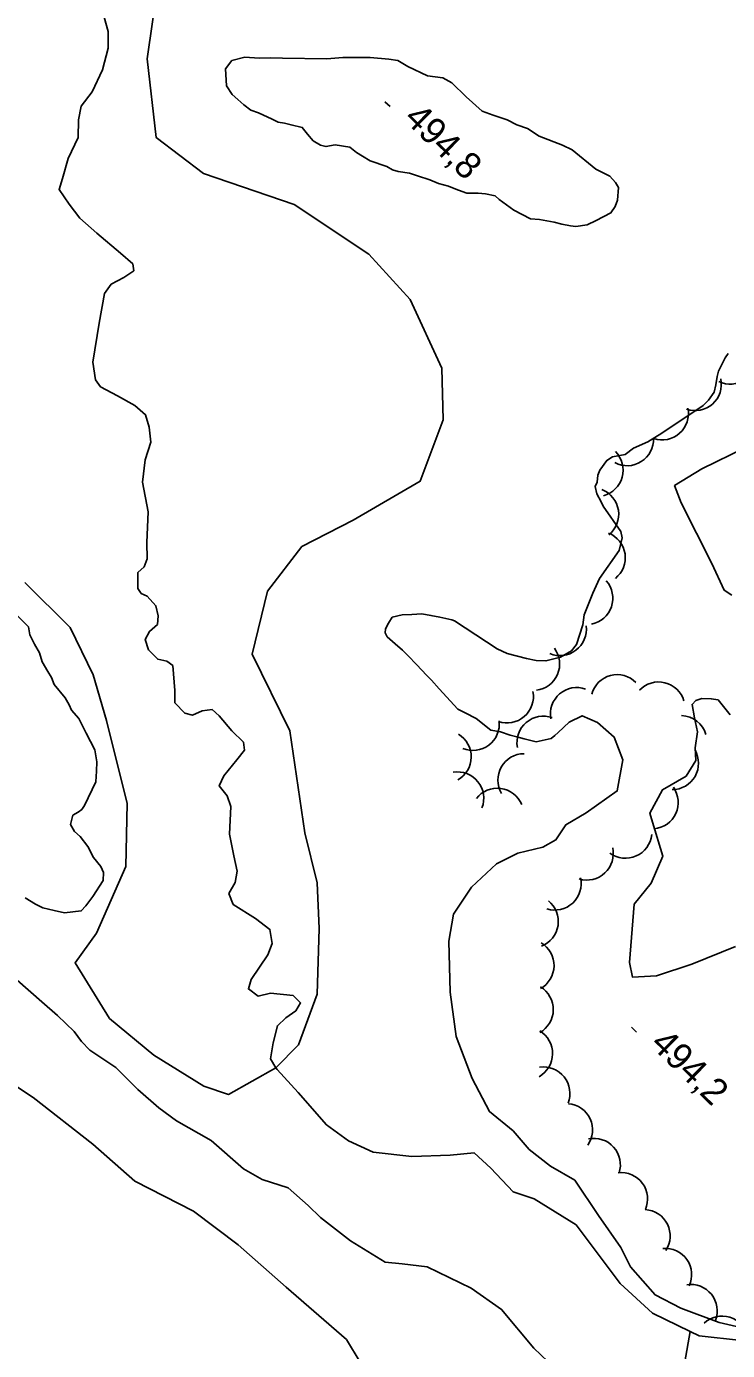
# Model space of a CAD drawing. Extents: x 642515 to 647219, y 6080136 to 6084356.
# Drawn here: x 643460.8 to 643540.5, y 6081462 to 6081612.4 of the extents above; entities that cross this region are included whole.
import ezdxf

# ---------------------------------------------------------------- set-up
doc = ezdxf.new("R2010")
doc.units = 0
for name, color, linetype in [('Level 19', 7, 'Continuous'), ('Level 2', 7, 'Continuous'), ('Level 3', 7, 'Continuous'), ('Level 4', 7, 'Continuous'), ('Level 44', 7, 'Continuous'), ('Level 7', 7, 'Continuous')]:
    doc.layers.add(name, color=color, linetype=linetype)

msp = doc.modelspace()

# ---------------------------------------------------------------- linework, layer by layer
at = {"layer": 'Level 19'}
msp.add_lwpolyline([(643540.96, 6081547.84), (643540.08, 6081548.38), (643538.67, 6081551.43), (643535.2, 6081558.32), (643534.43, 6081560.28), (643537.52, 6081562.18), (643542.51, 6081564.6)], dxfattribs=at)
at = {"layer": 'Level 2'}
msp.add_lwpolyline([(643518.08, 6081590.56), (643516.17, 6081591.56), (643514.52, 6081592.77), (643514.05, 6081593.18), (643512.95, 6081593.39), (643512.14, 6081593.5), (643511.29, 6081593.48), (643510.85, 6081593.49), (643510.32, 6081593.66), (643509.58, 6081593.93), (643508.75, 6081594.28), (643507.6, 6081594.6), (643506.65, 6081594.98), (643505.25, 6081595.45), (643504.31, 6081595.75), (643503.05, 6081595.94), (643502.39, 6081596.14), (643501.73, 6081596.5), (643499.87, 6081597.14), (643498.99, 6081597.68), (643498.32, 6081598.12), (643497.56, 6081598.71), (643495.89, 6081598.96), (643494.82, 6081598.77), (643494.21, 6081598.93), (643493.37, 6081599.44), (643492.75, 6081600.2), (643492.14, 6081600.96), (643490.87, 6081601.24), (643490.14, 6081601.43), (643489.41, 6081601.54), (643488.74, 6081601.9), (643487.16, 6081602.6), (643486.3, 6081602.9), (643485.49, 6081603.53), (643484.81, 6081604.13), (643484.17, 6081604.69), (643483.54, 6081605.69), (643483.41, 6081607.61), (643484.15, 6081608.54), (643485.61, 6081608.92), (643487.26, 6081608.83), (643488.55, 6081608.84), (643489.88, 6081608.81), (643494.94, 6081608.74), (643496.74, 6081608.9), (643499.84, 6081608.91), (643501.98, 6081608.69), (643502.99, 6081608.56), (643504.13, 6081607.87), (643506.37, 6081606.81), (643508.11, 6081606.57), (643509.15, 6081606.03), (643510.75, 6081604.41), (643512.59, 6081602.81), (643513.83, 6081602.33), (643515.43, 6081601.83), (643516.51, 6081601.26), (643517.71, 6081600.82), (643519.05, 6081599.94), (643521.69, 6081598.92), (643522.82, 6081598.39), (643525.5, 6081596.2), (643527.08, 6081595.42), (643527.73, 6081594.7), (643528.05, 6081594.12), (643527.94, 6081592.7), (643527.67, 6081591.96), (643527.2, 6081591.25), (643525.53, 6081590.37), (643524.52, 6081589.9), (643523.21, 6081589.7), (643522.6, 6081589.78), (643521.62, 6081589.95), (643520.76, 6081590.18), (643519.09, 6081590.51)], close=True, dxfattribs=at)
for points in [[(643540.51, 6081575.26), (643540.18, 6081574.8), (643539.93, 6081574.26), (643539.61, 6081573.63), (643539.44, 6081573.26), (643539.28, 6081572.65), (643539.14, 6081571.71), (643538.95, 6081570.9), (643538.29, 6081569.97), (643537.69, 6081569.37), (643533, 6081566.24), (643531.38, 6081565.25), (643529.78, 6081564.54), (643528.83, 6081563.79), (643527.4, 6081563.54), (643526.74, 6081563.13), (643525.94, 6081562.03), (643525.73, 6081561.46), (643525.63, 6081560.65), (643525.42, 6081560.15), (643525.6, 6081559.32), (643526.1, 6081558.43), (643526.34, 6081557.92), (643528.34, 6081555.04), (643528.47, 6081554.33), (643528.13, 6081552.9), (643525.89, 6081549.73), (643525.16, 6081548.04), (643524.16, 6081545.6), (643524, 6081544.46), (643523.31, 6081542.21), (643522.71, 6081541.52), (643521.47, 6081540.8), (643519.82, 6081540.36), (643518.73, 6081540.41), (643517.63, 6081540.62), (643515.42, 6081541.2), (643514.3, 6081541.72), (643509.42, 6081544.93), (643509.13, 6081545.04), (643507.78, 6081545.31), (643506.76, 6081545.52), (643505.71, 6081545.69), (643504.59, 6081545.62), (643503.5, 6081545.58), (643502.36, 6081545.31), (643501.92, 6081544.64), (643501.6, 6081544.01), (643501.55, 6081543.53), (643501.78, 6081543.1)], [(643458.19, 6081547.02), (643461.03, 6081544.24), (643461.21, 6081543.32), (643461.73, 6081542.27), (643462.28, 6081541.26), (643462.59, 6081540.24), (643463.22, 6081539.16), (643463.67, 6081538.46), (643463.97, 6081537.68), (643465.2, 6081536.15), (643465.65, 6081535.38), (643465.94, 6081534.76), (643466.76, 6081533.81), (643467.6, 6081532.17), (643468.57, 6081530.27), (643468.79, 6081528.88), (643468.78, 6081527.83), (643468.7, 6081526.62), (643467.4, 6081523.92), (643467.1, 6081523.5), (643466.68, 6081523.19), (643466.06, 6081522.83), (643465.81, 6081521.77), (643466.27, 6081520.99), (643466.91, 6081520.43), (643467.79, 6081519.28), (643468.44, 6081518.04), (643469.27, 6081517.01), (643469.56, 6081516.31), (643469.54, 6081515.42), (643468.34, 6081513.61), (643467.56, 6081512.56), (643467.04, 6081511.96), (643465.13, 6081511.75), (643463.94, 6081512.03), (643462.68, 6081512.31), (643461.84, 6081512.74), (643460.67, 6081513.46)], [(643501.78, 6081543.1), (643502.68, 6081542.31), (643503.54, 6081541.57), (643504.18, 6081540.93), (643505.13, 6081539.95), (643506.3, 6081538.7), (643506.82, 6081538.17), (643507.69, 6081537.18), (643509.82, 6081534.87), (643510.65, 6081534.45), (643511.9, 6081533.81), (643513.56, 6081532.51), (643514.66, 6081532.3), (643515.77, 6081531.94), (643516.5, 6081531.74), (643517.36, 6081531.52), (643518.71, 6081531.17), (643520.42, 6081531.56), (643520.84, 6081531.87), (643521.21, 6081532.22), (643522.46, 6081533.39), (643523.94, 6081534.13), (643525.68, 6081533.36), (643527.56, 6081531.71), (643528.54, 6081529.13), (643527.93, 6081525.59), (643524.4, 6081523.11), (643522.08, 6081521.75), (643520.95, 6081520.02), (643519.48, 6081519.2), (643516.63, 6081518.53), (643514.22, 6081517.33), (643511.35, 6081514.65), (643509.34, 6081511.58), (643508.78, 6081508.53), (643508.93, 6081502.75), (643509.63, 6081497.69), (643511.44, 6081492.95), (643513.42, 6081489.18), (643516.1, 6081486.98), (643517.93, 6081484.85), (643520.35, 6081482.96), (643523.11, 6081481.38), (643525.79, 6081477.37), (643528.33, 6081473.72), (643529.44, 6081471.54), (643532.23, 6081468.35), (643535.15, 6081466.86), (643539.52, 6081465.22), (643543.6, 6081464.28)], [(643541.34, 6081507.94), (643536.41, 6081505.93), (643532.4, 6081504.61), (643529.67, 6081504.43), (643529.32, 6081506.1), (643529.84, 6081512.73), (643531.77, 6081515.1), (643533.09, 6081518.17), (643531.94, 6081522.03), (643531.63, 6081523.05), (643533.06, 6081525.72), (643535.77, 6081527.27), (643536.86, 6081529.03), (643536.76, 6081530.47), (643537.04, 6081532.31), (643536.7, 6081533.9), (643536.43, 6081535.41), (643536.84, 6081535.88), (643537.55, 6081536.08), (643538.6, 6081536.07), (643539.37, 6081535.92), (643540.77, 6081534.25)], [(643459.74, 6081504.11), (643462.56, 6081501.65), (643464.35, 6081500.08), (643466.24, 6081498.28), (643467.05, 6081497.13), (643468, 6081496.14), (643470.95, 6081494.17), (643473.45, 6081491.68), (643475.84, 6081489.59), (643477.87, 6081488.12), (643481.8, 6081485.89), (643485.48, 6081482.68), (643487.57, 6081481.45), (643490.53, 6081480.52), (643492.83, 6081478.51), (643494.21, 6081477.15), (643497.61, 6081474.48), (643501.55, 6081472.09), (643503.5, 6081471.9), (643506.33, 6081471.53), (643511.32, 6081469.13), (643514.78, 6081466.71), (643518.46, 6081462.29), (643522.42, 6081458.53)], [(643534.31, 6081426.4), (643530.45, 6081432.48), (643528.5, 6081434.04), (643525.81, 6081435.79), (643522.3, 6081437.81), (643518.84, 6081440.39), (643516.3, 6081443.51), (643510.71, 6081447.8), (643501.84, 6081455.56), (643497.15, 6081463.28), (643490.32, 6081469.25), (643484.87, 6081474.03), (643479.79, 6081477.87), (643473.14, 6081481.28), (643468.36, 6081485.46), (643461.58, 6081490.79), (643456.21, 6081494.29)]]:
    msp.add_lwpolyline(points, dxfattribs=at)
at = {"layer": 'Level 3'}
for p, q in [((643501.54, 6081603.87), (643502.11, 6081603.31)), ((643529.54, 6081498.75), (643530.11, 6081498.19))]:
    msp.add_line(p, q, dxfattribs=at)
at = {"layer": 'Level 4'}
for points in [[(643472.99, 6081584.68), (643472.9, 6081585.44), (643471.49, 6081586.67), (643468.8, 6081588.95), (643466.87, 6081590.64), (643465.68, 6081592.22), (643464.52, 6081593.91), (643464.92, 6081595.15), (643465.54, 6081597.41), (643466.67, 6081599.82), (643466.74, 6081601.8), (643467.04, 6081603.35), (643468.26, 6081605.01), (643469.46, 6081607.51), (643470.11, 6081609.97), (643470.1, 6081611.86), (643469.63, 6081613.48)], [(643483.81, 6081513.95), (643484.53, 6081515.21), (643484.73, 6081516.47), (643484.37, 6081518.22), (643483.88, 6081520.69), (643484.04, 6081523.81), (643483.6, 6081525.03), (643482.71, 6081526.18), (643483.24, 6081527.3), (643484.69, 6081529.13), (643485.59, 6081530.24), (643485.45, 6081531.12), (643484.15, 6081532.4), (643482.71, 6081534.12), (643481.9, 6081534.83), (643480.78, 6081534.68), (643479.68, 6081534.2), (643478.82, 6081534.43), (643477.66, 6081535.6), (643477.68, 6081537.01), (643477.42, 6081539.82), (643476.74, 6081540.33), (643475.72, 6081540.55), (643474.68, 6081541.61), (643474.28, 6081542.79), (643474.78, 6081543.71), (643475.7, 6081544.5), (643475.79, 6081545.47), (643475.51, 6081546.62), (643474.52, 6081547.73), (643473.85, 6081548), (643473.45, 6081548.58), (643473.45, 6081550.4), (643474.17, 6081551.05), (643474.52, 6081551.96), (643474.47, 6081553.81), (643474.65, 6081557.29), (643473.98, 6081560.67), (643474.3, 6081563.19), (643474.93, 6081565.21), (643474.74, 6081566.89), (643474.32, 6081568.32), (643473.12, 6081569.36), (643471.15, 6081570.48), (643469.23, 6081571.49), (643468.66, 6081572.29), (643468.36, 6081574.29), (643469.07, 6081578.73), (643469.66, 6081582.08), (643470.43, 6081583.14), (643471.87, 6081583.92), (643472.99, 6081584.68)], [(643542.05, 6081463.16), (643537.22, 6081463.69), (643536.2, 6081464.19), (643531.93, 6081466.28), (643528.24, 6081469.66), (643523.25, 6081476.3), (643518.5, 6081479.25), (643516.11, 6081480.06), (643513.55, 6081482.75), (643511.67, 6081484.48), (643508.94, 6081484.22), (643504.6, 6081484.09), (643500.18, 6081484.57), (643497.39, 6081485.87), (643494.89, 6081487.68), (643491.67, 6081491.34), (643489.28, 6081493.96), (643489.15, 6081494.16), (643488.52, 6081495.16), (643488.84, 6081496.99), (643489.31, 6081498.92), (643490.26, 6081499.83), (643491.42, 6081500.63), (643491.96, 6081501.52), (643491.1, 6081502.35), (643488.55, 6081502.62), (643487.12, 6081502.28), (643486.02, 6081503.1), (643486.35, 6081504.17), (643488.22, 6081506.99), (643488.74, 6081508.28), (643488.47, 6081509.87), (643486.82, 6081511.09), (643484.29, 6081512.7), (643483.81, 6081513.95)], [(643536.2, 6081464.19), (643535.62, 6081460.76)]]:
    msp.add_lwpolyline(points, dxfattribs=at)
at = {"layer": 'Level 44'}
for centre, start, end in [((643540.78, 6081574.79), 244.0508, 4.0288), ((643536.75, 6081571.78), 251.6496, 11.6275), ((643533.01, 6081568.46), 251.6496, 11.6275), ((643529.05, 6081565.53), 242.2142, 2.1921), ((643525.59, 6081562.02), 284.7884, 44.7664), ((643525.09, 6081557.02), 308.6137, 68.5916), ((643525.84, 6081552.08), 308.6137, 68.5916), ((643524.42, 6081547.47), 281.3635, 41.3414), ((643521.42, 6081543.96), 247.1182, 7.0961), ((643518.38, 6081540), 276.7571, 36.735), ((643527.92, 6081535.8), 44.7995, 164.7774), ((643532.63, 6081534.97), 16.4855, 136.4634), ((643515.4, 6081536.31), 250.9032, 10.8811), ((643523.33, 6081534.34), 70.5391, 190.517), ((643511.52, 6081533.18), 247.3652, 7.3431), ((643519.53, 6081531.09), 70.5391, 190.517), ((643535.12, 6081531.15), 16.3721, 87.9208), ((643508.34, 6081529.46), 299.1489, 59.1268), ((643534.16, 6081528.74), 270.0474, 30.0253), ((643517.36, 6081526.82), 90.2911, 210.269), ((643509.76, 6081524.76), 338.7955, 98.7735), ((643514.3, 6081522.9), 22.4754, 142.4534), ((643531.85, 6081524.28), 275.202, 35.1799), ((643528.86, 6081520.95), 233.8492, 353.8272), ((643524.48, 6081518.47), 252.9459, 12.9239), ((643520.82, 6081515.06), 252.9459, 12.9239), ((643518.23, 6081510.76), 291.3502, 51.3282), ((643517.74, 6081505.76), 299.112, 59.0899), ((643517.66, 6081500.76), 299.112, 59.0899), ((643517.58, 6081495.76), 299.112, 59.0899), ((643519.54, 6081491.24), 338.412, 98.39), ((643522.12, 6081487.08), 324.904, 84.8819), ((643525.28, 6081483.13), 341.904, 101.882), ((643528.37, 6081479.25), 336.2414, 96.2193), ((643530.94, 6081475.04), 326.7522, 86.7302), ((643533.38, 6081470.64), 335.0054, 94.9833), ((643536.28, 6081466.54), 338.8559, 98.8338), ((643539.83, 6081462.95), 12.8898, 132.8677)]:
    msp.add_arc(centre, 3, start, end, dxfattribs=at)
at = {"layer": 'Level 7'}
msp.add_lwpolyline([(643460.62, 6081549.26), (643465.79, 6081544.14), (643468.4, 6081538.76), (643469.92, 6081533.59), (643472.24, 6081524.17), (643472.08, 6081517.01), (643468.77, 6081509.43), (643466.34, 6081506.05), (643470.26, 6081499.76), (643475.29, 6081495.58), (643480.95, 6081492.06), (643483.75, 6081491.12), (643489.15, 6081494.16), (643491.71, 6081496.74), (643493.82, 6081502.51), (643494.08, 6081509.97), (643493.85, 6081515.14), (643492.43, 6081520.84), (643490.74, 6081532.41), (643486.45, 6081541.14), (643488.18, 6081548.29), (643492.11, 6081553.37), (643497.94, 6081556.33), (643505.52, 6081560.77), (643508.15, 6081567.74), (643507.99, 6081573.6), (643504.41, 6081581.4), (643499.72, 6081586.56), (643491.22, 6081592.19), (643480.93, 6081595.7), (643475.55, 6081599.8), (643474.54, 6081608.74), (643475.77, 6081617.46)], dxfattribs=at)

# ---------------------------------------------------------------- texts
at = {"layer": 'Level 3'}
for s, p in [('494,8', (643503.57, 6081601.83)), ('494,2', (643531.57, 6081496.71))]:
    msp.add_text(s, height=3, rotation=315.59, dxfattribs=at).set_placement(p)

doc.saveas('drawing.dxf')
